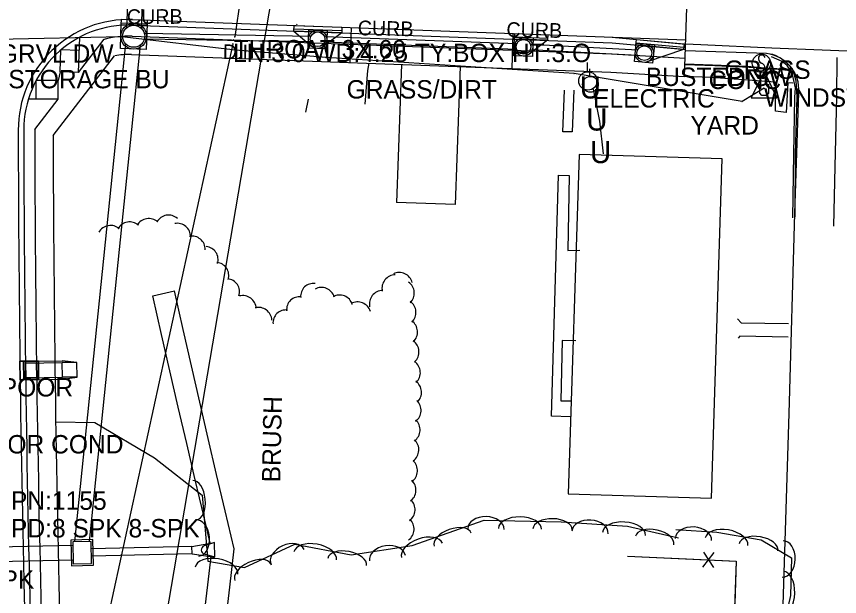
# Model space of a CAD drawing. Extents: x 978516 to 993312, y 1836504 to 1846212.
# Drawn here: x 992490.2 to 992713.9, y 1842443 to 1842600.5 of the extents above; entities that cross this region are included whole.
import ezdxf

# ---------------------------------------------------------------- set-up
doc = ezdxf.new("R2010")
doc.units = 0
for name, color, linetype in [('Default', 7, 'Continuous'), ('R_Drainage', 7, 'Continuous'), ('R_Proposed Road', 7, 'Continuous'), ('S_BUILDING', 7, 'Continuous'), ('S_CATCH_BASIN_ANNOT', 7, 'Continuous'), ('S_CURB', 7, 'Continuous'), ('S_CURB_ANNOT', 7, 'Continuous'), ('S_DRG_PT_SYM', 7, 'Continuous'), ('S_DRIVEWAY', 7, 'Continuous'), ('S_DROP_INLET_ANNOT', 7, 'Continuous'), ('S_EDGE_PAVEMENT', 7, 'Continuous'), ('S_FENCE', 7, 'Continuous'), ('S_FENCE_ANNOT', 7, 'Continuous'), ('S_FIBER_OPTIC_CABLE', 7, 'Continuous'), ('S_PAVEMENT_CROWN', 7, 'Continuous'), ('S_SANITARY_SEWER', 7, 'Continuous'), ('S_SECONDARY_CTL_ANNOT', 7, 'Continuous'), ('S_SIDEWALK', 7, 'Continuous'), ('S_SIGN', 7, 'Continuous'), ('S_STORM_SEWER', 7, 'Continuous'), ('S_STORM_SEWER_ANNOT', 7, 'Continuous'), ('S_SURVEY_TEXT_ANNOT', 7, 'Continuous'), ('S_TREE', 7, 'Continuous'), ('S_TREE_ANNOT', 7, 'Continuous'), ('S_UNDERGROUND_CABLE', 7, 'Continuous'), ('S_UNDERGROUND_CABLE_ANNOT', 7, 'Continuous'), ('S_UTILITY_POLE', 7, 'Continuous'), ('S_UTILITY_POLE_ANNOT', 7, 'Continuous'), ('S_UTL_PT_SYM', 7, 'Continuous')]:
    doc.layers.add(name, color=color, linetype=linetype)

msp = doc.modelspace()

# ---------------------------------------------------------------- linework, layer by layer
at = {"layer": 'R_Drainage'}
for p, q in [((992521.47, 1842633.71), (992520.14, 1842597.44)), ((992525.46, 1842633.57), (992524.13, 1842597.3)), ((992565.63, 1842596.54), (992570.42, 1842592.41)), ((992578.64, 1842596.56), (992565.64, 1842597.04)), ((992578.62, 1842596.07), (992573.54, 1842592.3)), ((992570.18, 1842593.59), (992524.95, 1842594.34)), ((992570.21, 1842595.09), (992524.97, 1842595.84)), ((992626.19, 1842593.07), (992573.93, 1842594.99)), ((992634.6, 1842594.51), (992625.61, 1842594.84)), ((992634.58, 1842594.02), (992629.51, 1842590.25)), ((992519.81, 1842593.15), (992505.96, 1842457.81)), ((992523.78, 1842592.68), (992509.99, 1842457.9)), ((992574.46, 1842591.71), (992569.46, 1842591.9)), ((992626.14, 1842591.57), (992573.87, 1842593.49)), ((992659.05, 1842591.39), (992629.91, 1842592.91)), ((992671.55, 1842592.06), (992658.6, 1842593.27)), ((992671.5, 1842591.56), (992661.67, 1842588.18)), ((992630.42, 1842589.66), (992625.43, 1842589.85)), ((992658.97, 1842589.89), (992629.83, 1842591.41)), ((992663.12, 1842587.82), (992658.14, 1842588.29)), ((992527.28, 1842524.63), (992533.13, 1842525.95)), ((992492.63, 1842506.86), (992491.13, 1842506.84)), ((992492.13, 1842506.85), (992502.63, 1842506.99)), ((992492.2, 1842501.85), (992492.13, 1842506.85)), ((992492.64, 1842506.36), (992502.64, 1842506.49)), ((992506.64, 1842506.54), (992502.63, 1842506.99)), ((992506.64, 1842506.54), (992502.64, 1842506.49)), ((992502.69, 1842502.49), (992502.64, 1842506.49)), ((992506.69, 1842502.54), (992506.64, 1842506.54)), ((992492.69, 1842502.36), (992492.64, 1842506.36)), ((992492.2, 1842501.85), (992502.69, 1842501.99)), ((992492.69, 1842502.36), (992502.69, 1842502.49)), ((992502.69, 1842501.99), (992506.69, 1842502.54)), ((992506.69, 1842502.54), (992502.69, 1842502.49)), ((992537.9, 1842456.52), (992544, 1842457.65)), ((992544, 1842457.65), (992541.22, 1842456.7)), ((992544.08, 1842453.65), (992544, 1842457.65)), ((992505.5, 1842456.8), (992443.02, 1842455.42)), ((992537.9, 1842456.52), (992510.52, 1842455.91)), ((992537.94, 1842454.52), (992537.9, 1842456.52)), ((992505.59, 1842452.8), (992443.11, 1842451.42)), ((992537.94, 1842454.52), (992510.57, 1842453.91)), ((992537.94, 1842454.52), (992544.08, 1842453.65)), ((992544.08, 1842453.65), (992541.26, 1842454.48))]:
    msp.add_line(p, q, dxfattribs=at)
for points in [[(992525.42, 1842591.51), (992518.43, 1842591.77), (992518.68, 1842598.76), (992525.68, 1842598.5)], [(992525.66, 1842598), (992518.67, 1842598.26), (992518.72, 1842599.76), (992525.72, 1842599.5)], [(992578.62, 1842596.07), (992565.63, 1842596.54), (992565.68, 1842598.04), (992578.67, 1842597.56)], [(992574.46, 1842591.71), (992569.46, 1842591.9), (992569.64, 1842596.89), (992574.64, 1842596.71)], [(992630.42, 1842589.66), (992625.43, 1842589.85), (992625.61, 1842594.84), (992630.61, 1842594.66)], [(992634.58, 1842594.02), (992625.59, 1842594.34), (992625.65, 1842595.84), (992634.64, 1842595.51)], [(992671.5, 1842591.56), (992658.56, 1842592.77), (992658.7, 1842594.26), (992671.64, 1842593.05)], [(992663.12, 1842587.82), (992658.14, 1842588.29), (992658.6, 1842593.27), (992663.58, 1842592.8)], [(992492.64, 1842506.86), (992492.7, 1842501.86), (992491.2, 1842501.84), (992491.14, 1842506.84)], [(992496.14, 1842506.9), (992496.19, 1842501.9), (992492.2, 1842501.85), (992492.14, 1842506.85)], [(992496.19, 1842501.9), (992496.14, 1842506.9), (992492.14, 1842506.85), (992492.2, 1842501.85)], [(992496.19, 1842501.9), (992496.14, 1842506.9), (992492.14, 1842506.85), (992492.2, 1842501.85)], [(992495.64, 1842506.39), (992495.69, 1842502.39), (992492.69, 1842502.36), (992492.64, 1842506.36)], [(992495.69, 1842502.39), (992495.64, 1842506.39), (992492.64, 1842506.36), (992492.69, 1842502.36)], [(992495.69, 1842502.39), (992495.64, 1842506.39), (992492.64, 1842506.36), (992492.69, 1842502.36)], [(992505.12, 1842451.29), (992511.12, 1842451.43), (992510.97, 1842458.42), (992504.97, 1842458.29)], [(992505.12, 1842451.29), (992511.12, 1842451.43), (992510.97, 1842458.42), (992504.97, 1842458.29)], [(992505.61, 1842451.8), (992510.61, 1842451.91), (992510.48, 1842457.91), (992505.48, 1842457.8)], [(992505.61, 1842451.8), (992510.61, 1842451.91), (992510.48, 1842457.91), (992505.48, 1842457.8)]]:
    msp.add_lwpolyline(points, close=True, dxfattribs=at)
for points in [[(992542.85, 1842457.44), (992541.09, 1842464.84), (992538.77, 1842474.68), (992536.47, 1842484.53), (992534.18, 1842494.38), (992531.91, 1842504.25), (992529.66, 1842514.12), (992527.28, 1842524.63)], [(992535.97, 1842335.33), (992544.8, 1842415.73), (992545.91, 1842425.64), (992547.03, 1842435.55), (992548.17, 1842445.45), (992549.39, 1842455.88), (992546.93, 1842466.22), (992544.61, 1842476.05), (992542.31, 1842485.89), (992540.03, 1842495.74), (992537.76, 1842505.59), (992535.51, 1842515.45), (992533.13, 1842525.95)], [(992491.13, 1842506.84), (992491.2, 1842501.84), (992492.7, 1842501.86), (992492.63, 1842506.86)], [(992529.18, 1842327.09), (992537.75, 1842406.46), (992538.84, 1842416.39), (992539.94, 1842426.31), (992541.07, 1842436.23), (992542.21, 1842446.14), (992543.11, 1842453.79)]]:
    msp.add_lwpolyline(points, dxfattribs=at)
for centre, radius in [((992522.05, 1842595.13), 3.5), ((992522.05, 1842595.13), 3.5), ((992522.05, 1842595.13), 3), ((992522.05, 1842595.13), 3), ((992572.05, 1842594.3), 2.5), ((992572.05, 1842594.3), 2.5), ((992572.05, 1842594.3), 2), ((992572.05, 1842594.3), 2), ((992628.02, 1842592.25), 2.5), ((992628.02, 1842592.25), 2.5), ((992628.02, 1842592.25), 2), ((992628.02, 1842592.25), 2), ((992660.86, 1842590.54), 2.5), ((992660.86, 1842590.54), 2.5), ((992660.86, 1842590.54), 2.5), ((992660.86, 1842590.54), 2), ((992660.86, 1842590.54), 2), ((992660.86, 1842590.54), 2)]:
    msp.add_circle(centre, radius, dxfattribs=at)
msp.add_arc((992541.59, 1842455.6), 1.17, 108.7959, 253.736, dxfattribs=at)
at = {"layer": 'R_Proposed Road'}
for p, q in [((992671.75, 1842584.2), (992673.63, 1842635.61)), ((992521.76, 1842599.65), (992672.11, 1842594.14)), ((992521.71, 1842598.15), (992652.07, 1842593.37)), ((992581.18, 1842597.47), (992580.83, 1842587.98)), ((992507.06, 1842585.27), (992507.42, 1842594.9)), ((992507.06, 1842585.27), (992514.02, 1842594.29)), ((992521.6, 1842595.15), (992651.96, 1842590.38)), ((992625.15, 1842595.86), (992624.8, 1842586.37)), ((992652.13, 1842594.87), (992672.07, 1842593.01)), ((992652.07, 1842593.37), (992672.02, 1842591.51)), ((992500.17, 1842568.14), (992516.88, 1842589.82)), ((992502.07, 1842585.45), (992502.29, 1842591.45)), ((992507.28, 1842591.27), (992502.29, 1842591.45)), ((992521.42, 1842590.15), (992651.78, 1842585.38)), ((992651.96, 1842590.38), (992671.93, 1842589.2)), ((992594.82, 1842587.47), (992593.45, 1842549.99)), ((992502.07, 1842585.45), (992501.52, 1842583.08)), ((992507.06, 1842585.27), (992502.07, 1842585.45)), ((992610.81, 1842586.88), (992609.44, 1842549.41)), ((992651.78, 1842585.38), (992671.75, 1842584.2)), ((992501.52, 1842583.08), (992495.52, 1842583.08)), ((992495.52, 1842578.08), (992495.52, 1842583.08)), ((992501.52, 1842578.08), (992501.52, 1842583.08)), ((992501.52, 1842578.08), (992493.44, 1842578.08)), ((992495.17, 1842569.84), (992501.52, 1842578.08)), ((992609.44, 1842549.41), (992593.45, 1842549.99))]:
    msp.add_line(p, q, dxfattribs=at)
for centre, radius, start, end in [((992520.67, 1842569.67), 30, 87.9024, 180.1112), ((992520.67, 1842569.67), 28.5, 87.9024, 180.1112), ((992520.67, 1842569.67), 25.5, 87.9024, 105.1165), ((992520.67, 1842569.67), 20.5, 87.9024, 100.6335), ((998202.23, 1842580.69), 5711.58, 180.11115, 183.02281), ((998202.23, 1842580.69), 5710.08, 180.11115, 183.02281), ((992520.67, 1842569.67), 25.5, 179.6047, 180.1112), ((998202.23, 1842580.69), 5707.08, 180.11115, 183.02281), ((998202.23, 1842580.69), 5702.08, 180.12608, 183.02281)]:
    msp.add_arc(centre, radius, start, end, dxfattribs=at)
at = {"layer": 'S_BUILDING'}
msp.add_lwpolyline([(992643.11, 1842563.03), (992640.18, 1842470.86), (992679.11, 1842469.63), (992682.03, 1842561.79)], close=True, dxfattribs=at)
at = {"layer": 'S_CURB'}
for points in [[(992566.51, 1842598.22), (992566.35, 1842598.4)], [(992589.5, 1842597.33), (992589.72, 1842597.86)], [(992592.3, 1842597.22), (992592.3, 1842597.22)], [(992701.24, 1842545.79), (992701.48, 1842563.06), (992701.75, 1842578.53), (992701.95, 1842581.11), (992701.35, 1842583.95), (992700.49, 1842585.99), (992699.67, 1842587.19), (992698.29, 1842588.29), (992695.38, 1842589.58)]]:
    msp.add_lwpolyline(points, dxfattribs=at)
at = {"layer": 'S_DRG_PT_SYM'}
msp.add_lwpolyline([(992549.24, 1842594.11), (992549.24, 1842594.16), (992549.24, 1842594.11), (992549.19, 1842594.11), (992549.24, 1842594.11), (992549.24, 1842594.06), (992549.24, 1842594.11), (992549.29, 1842594.11)], dxfattribs=at)
at = {"layer": 'S_DRIVEWAY'}
for points in [[(992585.93, 1842587.79), (992585.61, 1842585.79), (992584.9, 1842576.69)], [(992569.46, 1842578.02), (992568.73, 1842574.49)]]:
    msp.add_lwpolyline(points, dxfattribs=at)
at = {"layer": 'S_EDGE_PAVEMENT'}
for points in [[(992804.51, 1842588.78), (992784.25, 1842589.22), (992763.99, 1842589.66), (992743.45, 1842590.23), (992722.91, 1842590.8), (992709.23, 1842591.36), (992695.55, 1842591.92), (992676.23, 1842592.82), (992672.07, 1842593.01)], [(992694.08, 1842590.42), (992672.01, 1842591.19)], [(992701.82, 1842546.08), (992701.97, 1842563.1), (992702.43, 1842578.73), (992702.11, 1842583.06), (992701.09, 1842586.32), (992699.6, 1842587.81), (992697.85, 1842589.13), (992696.48, 1842589.86), (992695.53, 1842590.22)], [(992683.09, 1841927.49), (992684.24, 1841952.57), (992685.37, 1841996.83), (992687.17, 1842052.87), (992688.75, 1842114.89), (992690.9, 1842171.87), (992693.13, 1842226.16), (992693.94, 1842267.75), (992694.35, 1842305.35), (992696.03, 1842365.29), (992697.9, 1842417.52), (992700.23, 1842492.62), (992701.74, 1842547), (992702.86, 1842579.81)]]:
    msp.add_lwpolyline(points, dxfattribs=at)
msp.add_ellipse((992692.94, 1842580.52), major_axis=(-2.72, 9.58), ratio=0.998134, start_param=4.364729, end_param=5.891409, dxfattribs=at)
at = {"layer": 'S_FENCE'}
for p, q in [((992676.96, 1842455.04), (992679.64, 1842450.81)), ((992676.77, 1842450.95), (992679.83, 1842454.91))]:
    msp.add_line(p, q, dxfattribs=at)
for points in [[(992656.32, 1842453.94), (992676.3, 1842453.02)], [(992656.32, 1842453.94), (992685.83, 1842452.58), (992682.93, 1842370.9)], [(992680.3, 1842452.83), (992685.83, 1842452.58), (992685.32, 1842438.13)]]:
    msp.add_lwpolyline(points, dxfattribs=at)
at = {"layer": 'S_FIBER_OPTIC_CABLE'}
for p, q in [((992518.88, 1842594.98), (992459.48, 1842593.63)), ((992549.73, 1842591.37), (992518.88, 1842594.98)), ((992574.36, 1842589.33), (992549.73, 1842591.37)), ((992641.77, 1842585.04), (992574.36, 1842589.33)), ((992687.43, 1842577.43), (992641.77, 1842585.04)), ((992693.39, 1842580.98), (992687.43, 1842577.43))]:
    msp.add_line(p, q, dxfattribs=at)
at = {"layer": 'S_PAVEMENT_CROWN'}
msp.add_lwpolyline([(992712.38, 1842543.57), (992712.69, 1842559.71), (992713.19, 1842578.63), (992713.28, 1842589.32)], dxfattribs=at)
at = {"layer": 'S_SANITARY_SEWER'}
msp.add_line((992560.39, 1842610.92), (992527.83, 1842420.11), dxfattribs=at)
at = {"layer": 'S_SIDEWALK'}
for points in [[(992671.87, 1842587.45), (992679.98, 1842587.2), (992700.58, 1842586.15)], [(992671.88, 1842587.63), (992679.36, 1842587.33), (992688.91, 1842586.96), (992699.91, 1842585.92)], [(992701.25, 1842582.42), (992699.83, 1842582.5), (992699.45, 1842574.46), (992696.53, 1842574.77), (992696.53, 1842582.66), (992679.01, 1842583.93), (992671.75, 1842584.2)], [(992641.65, 1842580.52), (992641.28, 1842569.12), (992638.69, 1842569.17), (992639.17, 1842580.51)], [(992640.78, 1842491.79), (992635.59, 1842491.94), (992637.54, 1842557.4), (992640.44, 1842557.3), (992640.02, 1842536.95), (992643.36, 1842537.01)], [(992686.22, 1842518.33), (992687.21, 1842517.32), (992700.05, 1842517.14)], [(992699.97, 1842513.43), (992686.84, 1842513.7), (992686.4, 1842513.09)], [(992642.22, 1842512.42), (992638.5, 1842512.5), (992638.17, 1842496.13), (992641.13, 1842496.11)]]:
    msp.add_lwpolyline(points, dxfattribs=at)
at = {"layer": 'S_SIGN'}
msp.add_circle((992692.7, 1842587.79), 2.49, dxfattribs=at)
for centre, radius, start, end in [((992693.38, 1842589.12), 1.5, 167.1196, 241.9813), ((992692.77, 1842589.06), 0.95, 16.5258, 156.8957), ((992692.29, 1842586.45), 1.4, 358.6529, 73.7063), ((992692.54, 1842586.97), 1.28, 204.641, 335.359)]:
    msp.add_arc(centre, radius, start, end, dxfattribs=at)
at = {"layer": 'S_STORM_SEWER'}
for p, q in [((992555.31, 1842633.42), (992549.51, 1842594.97)), ((992549.05, 1842593.1), (992507.56, 1842403.16))]:
    msp.add_line(p, q, dxfattribs=at)
at = {"layer": 'S_TREE'}
for points in [[(992500.87, 1842490.38), (992511.47, 1842490.21), (992527.68, 1842480.6), (992540.63, 1842470.47), (992542.24, 1842452.54), (992552.19, 1842450.85), (992565.85, 1842457.16), (992581.14, 1842454.29), (992597.75, 1842456.78), (992617.29, 1842463.66), (992638.24, 1842463.28), (992656.31, 1842462.03), (992670.11, 1842458.89)], [(992669.38, 1842461.13), (992680.59, 1842460.45), (992692.62, 1842458.35), (992700.86, 1842453.48), (992700.63, 1842443.27), (992697.66, 1842430.45), (992690.3, 1842421.58), (992675.63, 1842425.79), (992666.87, 1842419.65), (992666.91, 1842407.2), (992676.73, 1842390.26), (992688.52, 1842387.56), (992698.78, 1842380.43), (992700.38, 1842366.52), (992702.09, 1842351.44), (992710.7, 1842341.45), (992712.51, 1842329.12)]]:
    msp.add_lwpolyline(points, dxfattribs=at)
for centre, major_axis, ratio, start_param, end_param in [((992520.95, 1842541.06), (-3.59, -0.61), 0.999693, 3.825789, 5.598989), ((992526.17, 1842541.98), (-3.59, -0.61), 0.999693, 3.825789, 5.598989), ((992531.54, 1842542.9), (-3.59, -0.61), 0.999693, 3.825789, 5.598989), ((992515.75, 1842540.09), (-3.59, -0.61), 0.999693, 3.825789, 5.598989), ((992533.89, 1842540.68), (1.57, 3.29), 0.990727, 5.142568, 6.915768), ((992537.88, 1842537.2), (1.57, 3.29), 0.990727, 5.142568, 6.915768), ((992541.39, 1842534.4), (2.68, 2.47), 0.978862, 5.240378, 7.013579), ((992544.29, 1842530.09), (2.68, 2.47), 0.978862, 5.240378, 7.013579), ((992594.21, 1842527.33), (-3.29, 1.56), 0.999424, 3.825789, 5.598989), ((992547.23, 1842525.64), (2.68, 2.47), 0.978862, 5.240378, 7.013579), ((992593.18, 1842526.67), (-2.28, -2.84), 0.999996, 3.825789, 5.598989), ((992571.01, 1842524.4), (2.43, -2.71), 0.9686, 2.284652, 4.057852), ((992573.1, 1842523.26), (-2.58, -2.57), 0.996354, 2.65943, 4.432631), ((992594.69, 1842525.36), (-0.27, 3.63), 0.999774, 3.825789, 5.598989), ((992551.72, 1842521.06), (-2.93, 2.16), 0.999412, 3.825789, 5.598989), ((992567.19, 1842520.77), (2.43, -2.71), 0.9686, 2.284652, 4.057852), ((992578, 1842521.21), (-2.58, -2.57), 0.996354, 2.65943, 4.432631), ((992589.76, 1842522.43), (-2.28, -2.84), 0.999996, 3.825789, 5.598989), ((992582.92, 1842519.32), (-2.58, -2.57), 0.996354, 2.65943, 4.432631), ((992595.15, 1842520.1), (-0.27, 3.63), 0.999774, 3.825789, 5.598989), ((992555.97, 1842517.84), (-2.93, 2.16), 0.999412, 3.825789, 5.598989), ((992563.5, 1842517.19), (2.43, -2.71), 0.9686, 2.284652, 4.057852), ((992595.57, 1842514.81), (-0.27, 3.63), 0.999774, 3.825789, 5.598989), ((992595.97, 1842509.39), (-0.27, 3.63), 0.999774, 3.825789, 5.598989), ((992596.34, 1842503.75), (-0.27, 3.63), 0.999774, 3.825789, 5.598989), ((992596.66, 1842498.42), (-0.27, 3.63), 0.999774, 3.825789, 5.598989), ((992596.55, 1842493.51), (0.22, 3.64), 0.999847, 3.825789, 5.598989), ((992596.26, 1842488.22), (0.22, 3.64), 0.999847, 3.825789, 5.598989), ((992595.92, 1842482.79), (0.22, 3.64), 0.999847, 3.825789, 5.598989), ((992595.55, 1842477.15), (0.22, 3.64), 0.999847, 3.825789, 5.598989), ((992538.62, 1842469.12), (-0.48, 5.32), 0.540699, 3.141593, 6.283185), ((992595.15, 1842471.83), (0.22, 3.64), 0.999847, 3.825789, 5.598989), ((992594.9, 1842466.55), (0.22, 3.64), 0.999847, 3.825789, 5.598989), ((992617.79, 1842461.27), (-4.95, 0.09), 0.685311, 3.141593, 6.283185), ((992627.06, 1842461.36), (-5.87, 0.1), 0.55008, 3.141593, 6.283185), ((992635.92, 1842461.2), (-5.35, 0.1), 0.540699, 3.141593, 6.283185), ((992539.28, 1842458.83), (-0.44, 4.94), 0.685311, 3.141593, 6.283185), ((992594.62, 1842461.26), (0.22, 3.64), 0.999847, 3.825789, 5.598989), ((992608.79, 1842458.41), (-5.04, -1.78), 0.540699, 3.141593, 6.283185), ((992646.08, 1842460.35), (-4.94, 0.34), 0.685311, 3.141593, 6.283185), ((992655.33, 1842459.97), (-5.85, 0.41), 0.55008, 3.141593, 6.283185), ((992674.19, 1842458.45), (-4.95, 0.3), 0.685311, 3.141593, 6.283185), ((992600.43, 1842455.47), (-5.54, -1.95), 0.55008, 3.141593, 6.283185), ((992663.68, 1842458.18), (-5.21, 1.19), 0.540699, 3.141593, 6.283185), ((992683.17, 1842457.85), (-5.78, 1.01), 0.55008, 3.141593, 6.283185), ((992691.9, 1842456.32), (-5.27, 0.92), 0.540699, 3.141593, 6.283185), ((992563.9, 1842453.64), (-4.5, -2.08), 0.685311, 3.141593, 6.283185), ((992571.37, 1842453.97), (-5.77, 1.09), 0.55008, 3.141593, 6.283185), ((992698.47, 1842453.16), (0.11, 4.95), 0.685311, 3.141593, 6.283185), ((992580.08, 1842452.33), (-5.25, 0.99), 0.540699, 3.141593, 6.283185), ((992591.01, 1842453.36), (-4.9, -0.73), 0.685311, 3.141593, 6.283185), ((992544.57, 1842449.99), (-5.79, 0.98), 0.55008, 3.141593, 6.283185), ((992554.44, 1842449.55), (-4.85, -2.24), 0.540699, 3.141593, 6.283185), ((992698.52, 1842443.9), (0.13, 5.87), 0.55008, 3.141593, 6.283185)]:
    msp.add_ellipse(centre, major_axis=major_axis, ratio=ratio, start_param=start_param, end_param=end_param, dxfattribs=at)
at = {"layer": 'S_UNDERGROUND_CABLE'}
for p, q in [((992693.41, 1842585.51), (992689.88, 1842578.42)), ((992693.41, 1842585.51), (992696.9, 1842578.42)), ((992646.93, 1842580.76), (992648.68, 1842572.05)), ((992692.21, 1842579.66), (992692.21, 1842582.1)), ((992694.57, 1842582.1), (992694.57, 1842579.66)), ((992689.88, 1842578.42), (992696.9, 1842578.42)), ((992692.83, 1842579), (992692.21, 1842579.66)), ((992694.03, 1842579), (992692.83, 1842579)), ((992694.57, 1842579.66), (992694.03, 1842579)), ((992648.68, 1842572.05), (992649.7, 1842563.21))]:
    msp.add_line(p, q, dxfattribs=at)
at = {"layer": 'S_UTILITY_POLE'}
for p, q in [((992645.38, 1842585.52), (992645.38, 1842588)), ((992646.07, 1842584.21), (992646.07, 1842586.32))]:
    msp.add_line(p, q, dxfattribs=at)
for centre, radius in [((992645.52, 1842583), 2.5), ((992646.19, 1842582.07), 2.13)]:
    msp.add_circle(centre, radius, dxfattribs=at)
at = {"layer": 'S_UTL_PT_SYM'}
for points in [[(992518.88, 1842594.98), (992518.88, 1842595.03), (992518.88, 1842594.98), (992518.83, 1842594.98), (992518.88, 1842594.98), (992518.88, 1842594.93), (992518.88, 1842594.98), (992518.93, 1842594.98)], [(992549.24, 1842594.11), (992549.24, 1842594.16), (992549.24, 1842594.11), (992549.19, 1842594.11), (992549.24, 1842594.11), (992549.24, 1842594.06), (992549.24, 1842594.11), (992549.29, 1842594.11)], [(992549.51, 1842594.97), (992549.51, 1842595.02), (992549.51, 1842594.97), (992549.46, 1842594.97), (992549.51, 1842594.97), (992549.51, 1842594.92), (992549.51, 1842594.97), (992549.56, 1842594.97)], [(992549.05, 1842593.1), (992549.05, 1842593.15), (992549.05, 1842593.1), (992549, 1842593.1), (992549.05, 1842593.1), (992549.05, 1842593.05), (992549.05, 1842593.1), (992549.1, 1842593.1)], [(992549.73, 1842591.37), (992549.73, 1842591.42), (992549.73, 1842591.37), (992549.68, 1842591.37), (992549.73, 1842591.37), (992549.73, 1842591.32), (992549.73, 1842591.37), (992549.78, 1842591.37)], [(992574.36, 1842589.33), (992574.36, 1842589.38), (992574.36, 1842589.33), (992574.31, 1842589.33), (992574.36, 1842589.33), (992574.36, 1842589.28), (992574.36, 1842589.33), (992574.41, 1842589.33)], [(992641.77, 1842585.04), (992641.77, 1842585.09), (992641.77, 1842585.04), (992641.72, 1842585.04), (992641.77, 1842585.04), (992641.77, 1842584.99), (992641.77, 1842585.04), (992641.82, 1842585.04)], [(992693.39, 1842580.98), (992693.39, 1842581.03), (992693.39, 1842580.98), (992693.34, 1842580.98), (992693.39, 1842580.98), (992693.39, 1842580.93), (992693.39, 1842580.98), (992693.44, 1842580.98)], [(992687.43, 1842577.43), (992687.43, 1842577.48), (992687.43, 1842577.43), (992687.38, 1842577.43), (992687.43, 1842577.43), (992687.43, 1842577.38), (992687.43, 1842577.43), (992687.48, 1842577.43)]]:
    msp.add_lwpolyline(points, dxfattribs=at)

# ---------------------------------------------------------------- texts
at = {"layer": 'Default'}
for p in [(992643.3, 1842578.21), (992645.05, 1842569.51), (992646.07, 1842560.67)]:
    msp.add_text('U', height=6, dxfattribs=at).set_placement(p)
at = {"layer": 'S_CATCH_BASIN_ANNOT'}
msp.add_text('THROAT 3X.60', height=5, dxfattribs=at).set_placement((992549.24, 1842589.11))
at = {"layer": 'S_CURB_ANNOT'}
for rotation, p in [(0.2576, (992520.21, 1842598.44)), (358.8373, (992582.93, 1842595.41)), (358.8373, (992623.34, 1842594.96))]:
    msp.add_text('CURB', height=4, rotation=rotation, dxfattribs=at).set_placement(p)
at = {"layer": 'S_DROP_INLET_ANNOT'}
msp.add_text('D.I.', height=4, rotation=358.8373, dxfattribs=at).set_placement((992546.25, 1842588.94))
at = {"layer": 'S_FENCE_ANNOT'}
msp.add_text("5' CHAINLINK/ POOR COND", height=5, dxfattribs=at).set_placement((992431.83, 1842481.81))
at = {"layer": 'S_SECONDARY_CTL_ANNOT'}
for s, p in [('PN:1155', (992488.7, 1842466.5)), ('PD:8 SPK 8-SPK', (992488.7, 1842459)), ('PD:8-SPK 8 SPK', (992443.75, 1842445.09))]:
    msp.add_text(s, height=5, dxfattribs=at).set_placement(p)
at = {"layer": 'S_STORM_SEWER_ANNOT'}
msp.add_text('LN:3.0 WD:4.25 TY:BOX HT:3.O', height=5, dxfattribs=at).set_placement((992549.05, 1842588.1))
at = {"layer": 'S_SURVEY_TEXT_ANNOT'}
for s, p in [('GRVL DW', (992485.38, 1842587.93)), (' GRASS', (992680.8, 1842583.54)), ('1-S-MTL STORAGE BU', (992460.12, 1842580.99)), ('BUSTED SW', (992661.26, 1842581.61)), ('CONC', (992678.34, 1842580.78)), ('GRASS/DIRT', (992579.93, 1842578.21)), (' YARD', (992671.56, 1842568.43)), ('1 STORY FRAME / POOR', (992426.48, 1842497.28))]:
    msp.add_text(s, height=5, dxfattribs=at).set_placement(p)
at = {"layer": 'S_TREE_ANNOT'}
msp.add_text('BRUSH', height=5, rotation=88.8373, dxfattribs=at).set_placement((992561.89, 1842473.92))
at = {"layer": 'S_UNDERGROUND_CABLE_ANNOT'}
msp.add_text('ELECTRIC', height=5, dxfattribs=at).set_placement((992646.93, 1842575.76))
at = {"layer": 'S_UTILITY_POLE_ANNOT'}
msp.add_text('WINDSTREAM', height=5, dxfattribs=at).set_placement((992693.41, 1842575.97))

doc.saveas('drawing.dxf')
